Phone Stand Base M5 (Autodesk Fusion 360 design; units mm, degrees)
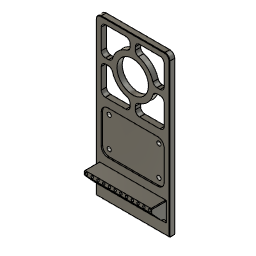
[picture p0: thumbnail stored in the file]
sketch "Sketch1" plane through (0, 0, 0) normal (0, 0, 1) x axis (1, 0, 0)
  line L1 (190.5, 0) -> (0, 0)
  line L2 (190.5, 88.9) -> (190.5, 0)
  line L3 (0, 88.9) -> (190.5, 88.9)
  line L4 (0, 0) -> (0, 88.9)
  point P1 (0, 0)
  point P2 (0, 0)
  point P3 (190.5, 0)
  point P5 (0, 88.9)
  horizontal L1
  vertical L2
  horizontal L3
  vertical L4
  coincident P1 P2
  dimension "d1" distance P2 P3 = 190.5
  dimension "d2" distance P2 P5 = 88.9
extrude "Extrude1" new body sketch "Sketch1" along normal blind 6.35
sketch "Sketch2" plane through (0, 0, 6.35) normal (0, 0, 1) x axis (-1, 0, 0)
  line L1 (0, 0) -> (0, -88.9)
  line L2 (-190.5, 0) -> (0, 0)
  line L3 (-190.5, -88.9) -> (-190.5, 0)
  line L4 (0, -88.9) -> (-190.5, -88.9)
  line L5 (-36.83, -85.09) -> (-19.05, -85.09)
  line L6 (-36.83, -3.81) -> (-36.83, -85.09)
  line L7 (-19.05, -3.81) -> (-36.83, -3.81)
  line L8 (-19.05, -85.09) -> (-19.05, -3.81)
  horizontal L5
  vertical L6
  horizontal L7
  vertical L8
  dimension "d5" distance L1 L8 = 19.05
  dimension "d6" distance L6 L8 = 17.78
  dimension "d7" distance L4 L5 = 3.81
  dimension "d8" distance L2 L7 = 3.81
extrude "Extrude2" add sketch "Sketch2" profile of L5 L6 L7 L8 along normal blind 17.78
fillet "Fillet1" radius 6
chamfer "Chamfer1" distance 12.7 distance 11.43
fillet "Fillet2" radius 6
chamfer "Chamfer2" distance 0.5 distance 0.508
fillet "Fillet4" radius 0.75
sketch "Sketch5" plane through (0, 0, 6.35) normal (0, 0, 1) x axis (-1, 0, 0)
  line L1 (-36.08, -85.09) -> (-13.05, -85.09)
  line L2 (-36.83, -4.56) -> (-36.83, -84.34)
  line L3 (-13.05, -3.81) -> (-36.08, -3.81)
  line L4 (-13.05, -85.09) -> (-13.05, -3.81)
  line L5 (-184.5, -0.5) -> (-0.5, -0.5)
  line L6 (-190, -82.9) -> (-190, -6)
  line L7 (-0.5, -88.4) -> (-184.5, -88.4)
  line L8 (-0.5, -0.5) -> (-0.5, -88.4)
  line L9 (0, -88.9) -> (-184.5, -88.9)
  line L10 (-190.5, -82.9) -> (-190.5, -6)
  line L11 (-184.15, -77.47) -> (-184.15, -52.705)
  line L12 (-154.305, -82.55) -> (-179.07, -82.55)
  line L13 (-184.15, -44.45) -> (-171.45, -44.45)
  line L14 (-190.5, -44.45) -> (-190, -44.45)
  line L15 (-179.07, -47.625) -> (-171.2508, -47.625)
  line L16 (-146.05, -82.55) -> (-146.05, -69.85)
  line L17 (-146.05, -88.9) -> (-146.05, -88.4)
  line L18 (-149.225, -77.47) -> (-149.225, -69.6508)
  line L19 (-149.225, -88.9) -> (-149.225, -88.4)
  arc A1 centre (-36.08, -84.34) radius 0.75 clockwise from (-36.08, -85.09) to (-36.83, -84.34)
  arc A2 centre (-36.08, -4.56) radius 0.75 clockwise from (-36.83, -4.56) to (-36.08, -3.81)
  arc A3 centre (-184.5, -6) radius 5.5 clockwise from (-190, -6) to (-184.5, -0.5)
  arc A4 centre (-184.5, -82.9) radius 5.5 clockwise from (-184.5, -88.4) to (-190, -82.9)
  circle C1 centre (-146.05, -44.45) radius 19.05
  circle C2 centre (-146.05, -44.45) radius 25.4
  arc A5 centre (-179.07, -77.47) radius 5.08 clockwise from (-179.07, -82.55) to (-184.15, -77.47)
  arc A6 centre (-154.305, -77.47) radius 5.08 clockwise from (-149.225, -77.47) to (-154.305, -82.55)
  arc A7 centre (-179.07, -52.705) radius 5.08 clockwise from (-184.15, -52.705) to (-179.07, -47.625)
  point P24 (-149.225, -69.6508)
  point P25 (-146.05, -69.85)
  point P26 (-171.2508, -47.625)
  point P27 (-171.45, -44.45)
  point P28 (-190.5, -44.45)
  point P29 (-184.15, -44.45)
  point P30 (-190, -44.45)
  point P31 (-146.05, -82.55)
  point P32 (-146.05, -88.4)
  point P33 (-149.225, -88.4)
  point P34 (-149.225, -88.9)
  point P35 (-146.05, -88.9)
  point P18 (-146.05, -44.45)
  coincident C2 P24
  coincident C2 P25
  coincident C2 P26
  coincident C2 P27
  coincident L10 P28
  coincident L11 P29
  coincident L6 P30
  collinear L13 L14
  coincident L12 P31
  coincident L7 P32
  collinear L16 L17
  coincident L7 P33
  collinear L18 L19
  coincident L9 P34
  coincident L9 P35
  tangent L12 A5
  tangent L11 A5
  tangent L18 A6
  tangent L12 A6
  tangent L11 A7
  tangent L15 A7
  dimension "d51" distance P18 L9 = 44.45
  dimension "d52" distance P18 L10 = 44.45
  dimension "d53" diameter C1 = 38.1
  dimension "d54" = 6.35
  dimension "d58" radius A5 = 5.08
  dimension "d59" radius A6 = 5.08
  dimension "d60" radius A7 = 5.08
extrude "Extrude5" cut sketch "Sketch5" profile of C1 C2 L19 L15 L11 L12 A5 A6 A7 no distance stored
fillet "Fillet5" radius 5
fillet "Fillet6" radius 5
circular_pattern "C-Pattern1" TotalAngle 360
fillet "Fillet7" radius 5
sketch "Sketch6" plane through (0, 0, 6.35) normal (0, 0, 1) x axis (-1, 0, 0)
  line L1 (-107.95, -77.47) -> (-107.95, -52.705)
  line L2 (-137.795, -82.55) -> (-113.03, -82.55)
  line L3 (-142.875, -73.7302) -> (-142.875, -77.47)
  line L4 (-113.03, -47.625) -> (-116.7698, -47.625)
  line L5 (-113.03, -6.35) -> (-137.795, -6.35)
  line L6 (-107.95, -36.195) -> (-107.95, -11.43)
  line L7 (-116.7698, -41.275) -> (-113.03, -41.275)
  line L8 (-142.875, -11.43) -> (-142.875, -15.1698)
  line L9 (-184.15, -11.43) -> (-184.15, -36.195)
  line L10 (-154.305, -6.35) -> (-179.07, -6.35)
  line L11 (-149.225, -15.1698) -> (-149.225, -11.43)
  line L12 (-179.07, -41.275) -> (-175.3302, -41.275)
  line L13 (-179.07, -82.55) -> (-154.305, -82.55)
  line L14 (-184.15, -52.705) -> (-184.15, -77.47)
  line L15 (-175.3302, -47.625) -> (-179.07, -47.625)
  line L16 (-149.225, -77.47) -> (-149.225, -73.7302)
  line L17 (-36.08, -85.09) -> (-13.05, -85.09)
  line L18 (-36.83, -4.56) -> (-36.83, -84.34)
  line L19 (-13.05, -3.81) -> (-36.08, -3.81)
  line L20 (-13.05, -85.09) -> (-13.05, -3.81)
  line L21 (-184.5, -0.5) -> (-0.5, -0.5)
  line L22 (-190, -82.9) -> (-190, -6)
  line L23 (-0.5, -88.4) -> (-184.5, -88.4)
  line L24 (-0.5, -0.5) -> (-0.5, -88.4)
  line L25 (-46.355, -82.55) -> (-98.425, -82.55)
  line L26 (-46.355, -6.35) -> (-46.355, -82.55)
  line L27 (-98.425, -6.35) -> (-46.355, -6.35)
  line L28 (-98.425, -82.55) -> (-98.425, -6.35)
  line L29 (0, -88.9) -> (-184.5, -88.9)
  arc A1 centre (-113.03, -52.705) radius 5.08 clockwise from (-113.03, -47.625) to (-107.95, -52.705)
  arc A2 centre (-113.03, -77.47) radius 5.08 clockwise from (-107.95, -77.47) to (-113.03, -82.55)
  arc A3 centre (-137.795, -77.47) radius 5.08 clockwise from (-137.795, -82.55) to (-142.875, -77.47)
  arc A4 centre (-137.875, -73.7302) radius 5 clockwise from (-142.875, -73.7302) to (-139.2196, -68.9144)
  arc A5 centre (-146.05, -44.45) radius 25.4 clockwise from (-121.5856, -51.2804) to (-139.2196, -68.9144)
  arc A6 centre (-116.7698, -52.625) radius 5 clockwise from (-121.5856, -51.2804) to (-116.7698, -47.625)
  arc A7 centre (-137.795, -11.43) radius 5.08 clockwise from (-142.875, -11.43) to (-137.795, -6.35)
  arc A8 centre (-113.03, -11.43) radius 5.08 clockwise from (-113.03, -6.35) to (-107.95, -11.43)
  arc A9 centre (-113.03, -36.195) radius 5.08 clockwise from (-107.95, -36.195) to (-113.03, -41.275)
  arc A10 centre (-116.7698, -36.275) radius 5 clockwise from (-116.7698, -41.275) to (-121.5856, -37.6196)
  arc A11 centre (-146.05, -44.45) radius 25.4 clockwise from (-139.2196, -19.9856) to (-121.5856, -37.6196)
  arc A12 centre (-137.875, -15.1698) radius 5 clockwise from (-139.2196, -19.9856) to (-142.875, -15.1698)
  arc A13 centre (-179.07, -36.195) radius 5.08 clockwise from (-179.07, -41.275) to (-184.15, -36.195)
  arc A14 centre (-179.07, -11.43) radius 5.08 clockwise from (-184.15, -11.43) to (-179.07, -6.35)
  arc A15 centre (-154.305, -11.43) radius 5.08 clockwise from (-154.305, -6.35) to (-149.225, -11.43)
  arc A16 centre (-154.225, -15.1698) radius 5 clockwise from (-149.225, -15.1698) to (-152.8804, -19.9856)
  arc A17 centre (-146.05, -44.45) radius 25.4 clockwise from (-170.5144, -37.6196) to (-152.8804, -19.9856)
  arc A18 centre (-175.3302, -36.275) radius 5 clockwise from (-170.5144, -37.6196) to (-175.3302, -41.275)
  arc A19 centre (-154.305, -77.47) radius 5.08 clockwise from (-149.225, -77.47) to (-154.305, -82.55)
  arc A20 centre (-179.07, -77.47) radius 5.08 clockwise from (-179.07, -82.55) to (-184.15, -77.47)
  arc A21 centre (-179.07, -52.705) radius 5.08 clockwise from (-184.15, -52.705) to (-179.07, -47.625)
  arc A22 centre (-175.3302, -52.625) radius 5 clockwise from (-175.3302, -47.625) to (-170.5144, -51.2804)
  arc A23 centre (-146.05, -44.45) radius 25.4 clockwise from (-152.8804, -68.9144) to (-170.5144, -51.2804)
  arc A24 centre (-154.225, -73.7302) radius 5 clockwise from (-152.8804, -68.9144) to (-149.225, -73.7302)
  circle C1 centre (-146.05, -44.45) radius 19.05
  arc A25 centre (-36.08, -84.34) radius 0.75 clockwise from (-36.08, -85.09) to (-36.83, -84.34)
  arc A26 centre (-36.08, -4.56) radius 0.75 clockwise from (-36.83, -4.56) to (-36.08, -3.81)
  arc A27 centre (-184.5, -6) radius 5.5 clockwise from (-190, -6) to (-184.5, -0.5)
  arc A28 centre (-184.5, -82.9) radius 5.5 clockwise from (-184.5, -88.4) to (-190, -82.9)
  horizontal L25
  vertical L26
  horizontal L27
  vertical L28
  dimension "d70" distance L25 L29 = 6.35
  dimension "d71" distance L25 L27 = 76.2
  dimension "d72" distance L6 L28 = 9.525
  dimension "d73" distance L18 L26 = 9.525
extrude "Extrude6" cut sketch "Sketch6" profile of L25 L26 L27 L28 against normal blind 1.6
fillet "Fillet8" radius 8
hole "Hole2" HoleDiameter 5.035 TipAngle 118
hole "Hole3" HoleDiameter 5.035 TipAngle 118
hole "Hole4" HoleDiameter 5.035 TipAngle 118
hole "Hole5" HoleDepth 30.48 HoleDiameter 5.035 TipAngle 118
hole "Hole6" HoleDepth 24.13 HoleDiameter 3 TipAngle 118 RefDim1 2.54 RefDim2 6.35
rectangular_pattern "R-Pattern2" countU 12 uSpaceDistance 76.2 vSpaceDistance 0
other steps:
thread "Thread2"
thread "Thread3"
thread "Thread4"
thread "Thread5"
